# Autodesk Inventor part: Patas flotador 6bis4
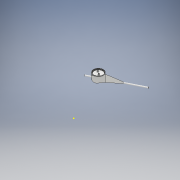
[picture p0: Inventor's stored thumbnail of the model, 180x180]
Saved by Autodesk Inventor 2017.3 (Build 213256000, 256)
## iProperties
Part Number: Patas flotador 6bis4
Material: Plástico ABS
Document SubType Name: Modeling
Designer: PABLO HERNANDEZ
Density: 1.06 g/cm^3
Appearance: Suave - Blanco
Mass: 4.28877 g
Surface Area: 39.5254 cm^2
Volume: 4.04601 cm^3
Author: M.RICO
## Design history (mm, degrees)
node "Geometría reparada1"
  feature "Base1"
sketch "Boceto1"
  geometry: C1 r 16 at (0, 0); 1 further point
  constraints: 1 centre point, 1 coincident
  dimensions: "d0" = 32 diameter of C1
extrude "Extrusión1" new body sketch "Boceto1" distance "d1" = 1; taper "d2" = 0 deg; dims "d93" = 1, "d94" = 0
sketch "Boceto2"
  geometry: C1 r 16 at (0, 0); C2 r 15 at (0, 0); C3 r 14 at (0, 0); 1 further point
  constraints: 3 centre point, 1 coincident
  dimensions: "d3" = 1 radial gap between concentric circles of C1 C2; "d4" = 1 radial gap between concentric circles of C2 C3
extrude "Extrusión2" join sketch "Boceto2" distance "d5" = 3; taper "d6" = 0 deg
sketch "Boceto3"
  geometry: C1 r 15 at (0, 0); C2 r 14 at (0, 0); 1 further point
  constraints: 2 centre point, 1 coincident
  dimensions: "d7" = 1 radial gap between concentric circles of C1 C2; "d123" = 30 diameter of C1
extrude "Extrusión3" join sketch "Boceto3" distance "d8" = 2; taper "d9" = 0 deg
sketch "Boceto4"
  geometry: C1 r 16 at (0, 0); 1 further point
  constraints: 1 centre point, 1 coincident
extrude "Extrusión4" cut sketch "Boceto4" distance "d10" = 0.5; taper "d11" = 0 deg
sketch "Boceto7"
  geometry: L1 (1.5, -15.93)-(1.5, 15.93); L2 (-1.5, -15.93)-(-1.5, 15.93); A1 r 16 centre (0, 0) between (1.5, 15.93) and (-1.5, 15.93); A2 r 16 centre (0, 0) between (-1.5, -15.93) and (1.5, -15.93); 2 further points
  constraints: 4 end point, 4 point on circle, 2 centre point, 1 coincident
extrude "Extrusión7" join sketch "Boceto7" distance "d63" = 25; taper "d64" = 0 deg
fillet "Empalme2" dims "d95" = 3
fillet "Empalme3" dims "d96" = 0.5
sketch "Boceto13"
  geometry: C1 r 1.2 at (-6, 0) reference; C2 r 1.75 at (-6, 0); C3 r 1.2 at (6, 0) reference; C4 r 1.75 at (6, 0); 1 further point
  constraints: 2 centre point, 2 coincident
  dimensions: "d118" = 3.5 diameter of C2; "d119" = 3.5 diameter of C4
extrude "Extrusión10" join sketch "Boceto13" distance "d120" = 3; taper "d121" = 0 deg
fillet "Empalme4" dims "d122" = 1
sketch "Boceto14"
  geometry: 1 further point
sketch "Boceto15"
  geometry: C1 r 1.2 at (6, 0) reference; C2 r 2.5 at (6, 0); C3 r 1.2 at (-6, 0) reference; C4 r 2.5 at (-6, 0); 1 further point
  constraints: 2 centre point, 2 coincident
  dimensions: "d124" = 5 diameter of C2; "d125" = 5 diameter of C4
extrude "Extrusión11" cut sketch "Boceto15" distance "d126" = 10; taper "d127" = 0 deg
hole "Agujero7" diameter "d151" = 2.4; stored, may be unused: countersink angle "d155" = 90 deg, drill point angle "d157" = 118 deg; dims "d149" = 10, "d150" = 10, "d152" = 6, "d153" = 4, "d154" = 2, "d156" = 8
hole "Agujero8" diameter "d160" = 2.4; stored, may be unused: countersink angle "d164" = 90 deg, drill point angle "d166" = 118 deg; dims "d158" = 10, "d159" = 10, "d161" = 6, "d162" = 4, "d163" = 2, "d165" = 8
node "Eje de trabajo1"
feature "Desplazar cuerpo1"
feature "Compuesta1"
feature "Desplazar cuerpo2"
node "Eje de trabajo2"
feature "Desplazar cuerpo3"
node "Plano de trabajo6"
sketch "Boceto27"
  geometry: L1 (0, 0)-(-149.324, -102.291); L2 (-134.431, -229.557)-(132.044, -87.232); L3 (-65.839, 96.112)-(-215.163, -6.179); L4 (-53.123, 77.549)-(-202.447, -24.742); L5 (-53.123, 77.549)-(-215.163, -6.179); C1 r 14 at (-149.324, -102.291) reference
  constraints: 10 end point, 2 parallel, 1 point on line
  dimensions: "d194" = 116.5 distance between parallel lines of L1 L3; "d195" = 94 distance between parallel lines of L1 L4
node "Plano de trabajo7"
node "Plano de trabajo8"
sketch "Boceto28"
  geometry: C1 r 2 at (0, 0); 1 further point
  constraints: 1 centre point
  dimensions: "d177" = 4 diameter of C1
extrude "Extrusión14" join sketch "Boceto28" stored distance "d178" = 10; taper "d179" = 0 deg
sketch "Boceto29"
  geometry: L1 (-0.28, 0)-(0, 0) reference; L2 (0, 0)-(-102.216, -91.987); L3 (-0.28, 23.165)-(-0.28, 0) reference; L4 (0, 23.165)-(0, 0) reference; L5 (0, 0)-(0, 23.165); L6 (0, 23.165)-(-105.015, -89.134); C1 r 2 at (-103.554, -90.5) reference; A1 r 2 centre (-103.554, -90.5) between (-102.216, -91.987) and (-105.015, -89.134) reference; 1 further point
  constraints: 6 end point, 2 point on circle, 2 tangent, 1 collinear
extrude "Extrusión15" join sketch "Boceto29" stored distance "d180" = 10; taper "d181" = 0 deg
node "Plano de trabajo9"
sketch "Boceto30"
  geometry: L1 (1.356, 23.165)-(1.356, 0) reference; L2 (1.356, 0)-(-130.469, -92.139); L3 (1.356, 0)-(1.356, 23.165); L4 (1.356, 23.165)-(-132.897, -88.965); A1 r 2 centre (-131.615, -90.5) between (-130.469, -92.139) and (-132.897, -88.965) reference; A2 r 2 centre (-131.615, -90.5) between (-132.897, -88.965) and (-130.469, -92.139); 1 further point
  constraints: 6 end point, 4 point on circle, 2 tangent, 1 centre point, 1 coincident, 1 vertical
extrude "Extrusión16" join sketch "Boceto30" distance "d182" = 3; taper "d183" = 0 deg
node "Plano de trabajo10"
sketch "Boceto31"
  geometry: L1 (-7.175, -6.405)-(170.651, -6.405); L2 (170.651, -6.405)-(170.651, 129.955); L3 (170.651, 129.955)-(-7.175, 129.955); L4 (-7.175, 129.955)-(-7.175, -6.405); 1 further point
  constraints: 8 end point, 2 parallel, 1 horizontal, 1 perpendicular
extrude "Extrusión17" cut sketch "Boceto31" distance "d185" = 150; taper "d186" = 0 deg
sketch "Boceto32"
  geometry: C1 r 1 at (0, 0); 1 further point
  constraints: 1 centre point
  dimensions: "d187" = 2 diameter of C1
extrude "Extrusión18" cut sketch "Boceto32" distance "d188" = 6; taper "d189" = 0 deg
sketch "Boceto33"
  geometry: L1 (31.859, 0)-(0, 0) reference; L2 (0, -3)-(31.859, -3) reference; L3 (31.859, 0)-(0, 0); L4 (0, 0)-(0, -3); L5 (0, -3)-(31.859, -3); L6 (31.859, -3)-(31.859, 0); 1 further point
  constraints: 8 end point, 2 parallel, 1 horizontal, 1 perpendicular
extrude "Extrusión19" cut sketch "Boceto33" distance "d191" = 24; taper "d192" = 0 deg
node "Plano de trabajo11"
node "Plano de trabajo12"
mirror "Simetría1"
fillet "Empalme6" dims "d197" = 14
node "Sólido1"
feature "Patrón de Sólido1:1"
node "Sólido2"
feature "Patrón de Sólido3:2"
node "Sólido4"
node "Sup1"
node "Sólido3"
other parameters: "sa_0" = 4, "d167" = 90 deg, "d168" = -149.324, "d169" = -102.291, "d170" = 0, "d171" = 9.86699, "d184" = 147, "d193" = 90 deg, "d196" = 90 deg
